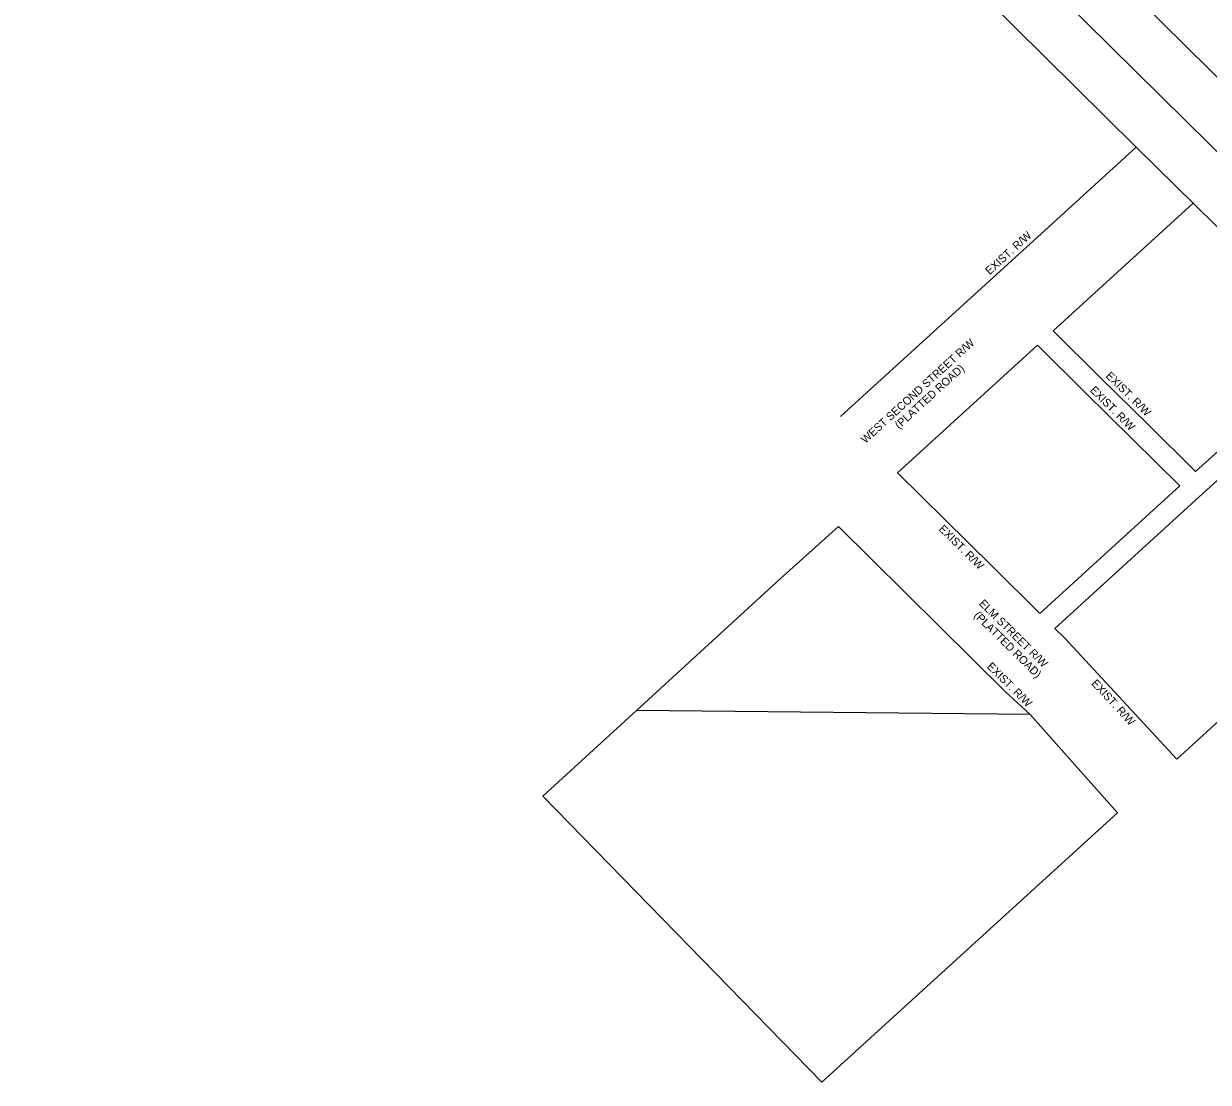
# Model space of a CAD drawing. Extents: x 1658728 to 1662455, y 669586 to 671174.
# Drawn here: x 1660345 to 1661233, y 669586 to 670380 of the extents above; entities that cross this region are included whole.
import ezdxf

# ---------------------------------------------------------------- set-up
doc = ezdxf.new("R2010")
doc.units = 0
for name, color, linetype in [('R_Grid', 7, 'Continuous'), ('S_DRIVEWAY', 7, 'Continuous'), ('S_EDGE_PAVEMENT', 7, 'Continuous'), ('S_SHOULDER', 7, 'Continuous')]:
    doc.layers.add(name, color=color, linetype=linetype)

msp = doc.modelspace()

# ---------------------------------------------------------------- linework, layer by layer
at = {"layer": 'S_DRIVEWAY'}
for p, q in [((1661404.92, 670177.11), (1660401.45, 671169.67)), ((1661179.46, 670287.61), (1660345.19, 671112.79))]:
    msp.add_line(p, q, dxfattribs=at)
at = {"layer": 'S_EDGE_PAVEMENT'}
msp.add_line((1661376.17, 670149.3), (1660373.32, 671141.23), dxfattribs=at)
at = {"layer": 'S_SHOULDER'}
for p, q in [((1661347.41, 670121.48), (1661179.46, 670287.61)), ((1661117.18, 670149.75), (1661222.11, 670245.41)), ((1661117.18, 670149.75), (1661152.72, 670114.58)), ((1661223.82, 670044.26), (1661329.21, 670139.48)), ((1661152.72, 670114.58), (1661188.31, 670079.46)), ((1661188.31, 670079.46), (1661223.82, 670044.26)), ((1661192.34, 669993.93), (1661155.39, 669960.25)), ((1661155.39, 669960.25), (1661118.44, 669926.56)), ((1661118.44, 669926.56), (1661125.71, 669919.37)), ((1661125.71, 669919.37), (1661209.76, 669828.52)), ((1661209.76, 669828.52), (1661246.71, 669862.2))]:
    msp.add_line(p, q, dxfattribs=at)
for points in [[(1661179.46, 670287.61), (1661102.65, 670217.59)], [(1661102.65, 670217.59), (1660957.76, 670085.49)], [(1661339.94, 670128.87), (1661303.18, 670094.99), (1661266.23, 670061.31), (1661229.28, 670027.62)], [(1661229.28, 670027.62), (1661192.34, 669993.93)], [(1660804.73, 669864.9), (1660734.38, 669800.76), (1660943.72, 669585.98), (1661165.42, 669788.09), (1661099.76, 669861.87)]]:
    msp.add_lwpolyline(points, dxfattribs=at)
for points in [[(1661000.42, 670043.3), (1661105.35, 670138.97), (1661140.9, 670103.8), (1661176.45, 670068.64), (1661212, 670033.48), (1661107.06, 669937.81), (1661071.51, 669972.97), (1661035.97, 670008.14)], [(1661099.76, 669861.87), (1660804.73, 669864.9), (1660912.35, 669963.67), (1660956.08, 670002.87), (1661081.37, 669878.94)]]:
    msp.add_lwpolyline(points, close=True, dxfattribs=at)

# ---------------------------------------------------------------- texts
at = {"layer": 'R_Grid'}
for s, rotation, p in [('EXIST. R/W', 42.35483, (1661069.48, 670191.41)), ('WEST SECOND STREET R/W', 42.35483, (1660976.33, 670064.83)), ('(PLATTED ROAD)', 42.35483, (1661001.67, 670075.75)), ('EXIST. R/W', 315.37359, (1661156.08, 670115.48)), ('EXIST. R/W', 315.31331, (1661144.26, 670104.7)), ('EXIST. R/W', 315.31331, (1661030.88, 670000.5)), ('ELM STREET R/W', 315.31331, (1661061.02, 669944.62)), ('(PLATTED ROAD)', 315.31331, (1661057.18, 669935.76)), ('EXIST. R/W', 315.31331, (1661066.95, 669897.42)), ('EXIST. R/W', 312.77374, (1661145.34, 669884.89))]:
    msp.add_text(s, height=6, rotation=rotation, dxfattribs=at).set_placement(p)

doc.saveas('drawing.dxf')
